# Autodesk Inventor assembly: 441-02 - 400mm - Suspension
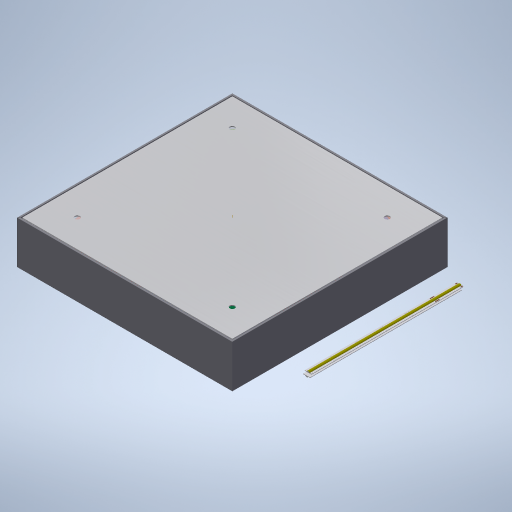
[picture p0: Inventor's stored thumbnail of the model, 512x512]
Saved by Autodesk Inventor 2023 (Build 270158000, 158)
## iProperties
Created: 2022-07
Part Number: 441-02 - 400mm - Suspension
Document SubType Name: Assembly
Designer: DarkStudio
Engineer: DarkStudio
Description: SQUARE MOON 400mm
Manager: DarkStudio
Company: DARK
Mass: 57087.8 g
Surface Area: 45581 cm^2
Volume: 7755.55 cm^3
Density: 7.3609 g/cm^3
Author: DarkStudio
Revision Number: V2
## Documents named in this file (49)
- C:\Users\Stage\Desktop\Stage Karsten\armatures\450 - VIDRYA\450_KARSTEN\3D_LIB_VYDRIA.iam
- D:\Dropbox\003 - DARK 2022\DARK - INVENTOR LOCAL\PROJECT CURRENT\441 - SQUARE MOON\441-001.ipt
- D:\Dropbox\003 - DARK 2022\DARK - INVENTOR LOCAL\PROJECT CURRENT\441 - SQUARE MOON\441-002.ipt
- D:\Dropbox\003 - DARK 2022\DARK - INVENTOR LOCAL\PROJECT CURRENT\441 - SQUARE MOON\441-003.ipt
- D:\Dropbox\003 - DARK 2022\DARK - INVENTOR LOCAL\PROJECT CURRENT\441 - SQUARE MOON\441-004.ipt
- D:\Dropbox\003 - DARK 2022\DARK - INVENTOR LOCAL\PROJECT CURRENT\441 - SQUARE MOON\441-05 + Lightplate and scews.iam
- D:\Dropbox\003 - DARK 2022\DARK - INVENTOR LOCAL\PROJECT CURRENT\441 - SQUARE MOON\441-007.ipt
- D:\Dropbox\003 - DARK 2022\DARK - INVENTOR LOCAL\PROJECT CURRENT\441 - SQUARE MOON\544COB-IP20-2700 - sectie  - 176,4.ipt
- C:\Users\Stage\Desktop\Stage Karsten\armatures\450 - VIDRYA\450-001.ipt
- C:\Users\Stage\Desktop\Stage Karsten\armatures\450 - VIDRYA\450-300 - Sub Assembly Straight Bracket and scew.iam
- C:\Users\Stage\Desktop\Stage Karsten\armatures\450 - VIDRYA\450-002.ipt
- C:\Users\Stage\Desktop\Stage Karsten\armatures\450 - VIDRYA\450-019.ipt
- C:\Users\Stage\Desktop\Stage Karsten\armatures\450 - VIDRYA\450-006.ipt
- C:\Users\Stage\Desktop\Stage Karsten\armatures\450 - VIDRYA\450-008.ipt
- C:\Users\Stage\Desktop\Stage Karsten\armatures\450 - VIDRYA\450-009.ipt
- C:\Users\Stage\Desktop\Stage Karsten\armatures\450 - VIDRYA\450-010.ipt
- C:\Users\Stage\Desktop\Stage Karsten\armatures\450 - VIDRYA\450-011.ipt
- C:\Users\Stage\Desktop\Stage Karsten\armatures\450 - VIDRYA\450-100 - Back-lit panel 295x1195.ipt
- C:\Users\Stage\Desktop\Stage Karsten\armatures\450 - VIDRYA\450-018.ipt
- C:\Users\Stage\Desktop\Stage Karsten\armatures\450 - VIDRYA\450-101 - Back-lit panel UGR-diffusor.ipt
- C:\Users\Stage\Desktop\Stage Karsten\armatures\450 - VIDRYA\450-102 - Back-lit panel diffusor.ipt
- C:\Users\Stage\Desktop\Stage Karsten\armatures\450 - VIDRYA\450-200 - Sub Assembly Brackets and scews DIN916.iam
- C:\Users\Stage\Desktop\Stage Karsten\armatures\450 - VIDRYA\450-004.ipt
- C:\Users\NUUV\Dropbox\003 - DARK 2022\DARK - INVENTOR LOCAL\PROJECT CURRENT\441 - SQUARE MOON - ACTIEF\441-200 - Sub Assembly Brackets and scews ISO7380.iam
- C:\Users\NUUV\Dropbox\003 - DARK 2022\DARK - INVENTOR LOCAL\PROJECT CURRENT\450 - VIDRYA\450-001.ipt
- C:\Users\NUUV\Dropbox\003 - DARK 2022\DARK - INVENTOR LOCAL\PROJECT CURRENT\450 - VIDRYA\450-300 - Sub Assembly Straight Bracket and scew.iam
- C:\Users\NUUV\Dropbox\003 - DARK 2022\DARK - INVENTOR LOCAL\PROJECT CURRENT\450 - VIDRYA\450-002.ipt
- C:\Users\NUUV\Dropbox\003 - DARK 2022\DARK - INVENTOR LOCAL\PROJECT CURRENT\450 - VIDRYA\450-019.ipt
- C:\Users\NUUV\Dropbox\003 - DARK 2022\DARK - INVENTOR LOCAL\PROJECT CURRENT\450 - VIDRYA\450-006.ipt
- C:\Users\NUUV\Dropbox\003 - DARK 2022\DARK - INVENTOR LOCAL\PROJECT CURRENT\450 - VIDRYA\450-008.ipt
- C:\Users\NUUV\Dropbox\003 - DARK 2022\DARK - INVENTOR LOCAL\PROJECT CURRENT\450 - VIDRYA\450-009.ipt
- C:\Users\NUUV\Dropbox\003 - DARK 2022\DARK - INVENTOR LOCAL\PROJECT CURRENT\450 - VIDRYA\450-010.ipt
- C:\Users\NUUV\Dropbox\003 - DARK 2022\DARK - INVENTOR LOCAL\PROJECT CURRENT\450 - VIDRYA\450-011.ipt
- C:\Users\NUUV\Dropbox\003 - DARK 2022\DARK - INVENTOR LOCAL\PROJECT CURRENT\450 - VIDRYA\450-100 - Back-lit panel 295x1195.ipt
- C:\Users\NUUV\Dropbox\003 - DARK 2022\DARK - INVENTOR LOCAL\PROJECT CURRENT\450 - VIDRYA\450-018.ipt
- C:\Users\NUUV\Dropbox\003 - DARK 2022\DARK - INVENTOR LOCAL\PROJECT CURRENT\450 - VIDRYA\450-101 - Back-lit panel UGR-diffusor.ipt
- C:\Users\NUUV\Dropbox\003 - DARK 2022\DARK - INVENTOR LOCAL\PROJECT CURRENT\450 - VIDRYA\450-102 - Back-lit panel diffusor.ipt
- C:\Users\NUUV\Dropbox\003 - DARK 2022\DARK - INVENTOR LOCAL\LIBRARY\ALLERLEI\Splitter Diam 2 B diam. 1.2 O.ipt
- C:\Users\NUUV\Dropbox\003 - DARK 2022\DARK - INVENTOR LOCAL\LIBRARY\ALLERLEI\190-1000-000008.ipt
- C:\Users\NUUV\Dropbox\003 - DARK 2022\DARK - INVENTOR LOCAL\LIBRARY\ALLERLEI\190-1000-000007.ipt
- C:\Users\NUUV\Dropbox\003 - DARK 2022\DARK - INVENTOR LOCAL\LIBRARY\SUSPENSION KITS\190-2012-001500.ipt
- C:\Users\NUUV\Dropbox\003 - DARK 2022\DARK - INVENTOR LOCAL\PROJECT CURRENT\450 - VIDRYA\450-200 - Sub Assembly Brackets and scews DIN916.iam
- C:\Users\NUUV\Dropbox\003 - DARK 2022\DARK - INVENTOR LOCAL\LIBRARY\KABEL ONDERDELEN\Steab - Strain Relief 5331-5.ipt
- C:\Users\NUUV\Dropbox\003 - DARK 2022\DARK - INVENTOR LOCAL\PROJECT CURRENT\225 - PLAFONDPOTJES\225-100.iam
- C:\Users\NUUV\Dropbox\003 - DARK 2022\DARK - INVENTOR LOCAL\PROJECT CURRENT\225 - PLAFONDPOTJES\225-500.iam
- C:\Users\NUUV\Dropbox\003 - DARK 2022\DARK - INVENTOR LOCAL\PROJECT CURRENT\225 - PLAFONDPOTJES\225-640.iam
- C:\Users\NUUV\Dropbox\003 - DARK 2022\DARK - INVENTOR LOCAL\PROJECT CURRENT\225 - PLAFONDPOTJES\225-800.iam
- C:\Users\NUUV\Dropbox\003 - DARK 2022\DARK - INVENTOR LOCAL\PROJECT CURRENT\450 - VIDRYA\450-004.ipt
- C:\Users\NUUV\Dropbox\003 - DARK 2022\DARK - INVENTOR LOCAL\LIBRARY\BEVESTIGING\DIN 7991\M4\DIN 7991 M4 x 8 A2.ipt
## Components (20 placed, 7 different names)
1. 441-002:1 — Mate:3, Mate:4, Flush:6
2. 441-003:1 — Mate:5, Mate:6, Flush:7
3. 441-004:1 — Mate:7, Mate:8, Mate:9, Mate:22
4. 441-007:1 — Mate:23, Mate:24, Mate:25
5. 441-001:1 — Flush:1, Flush:2, Flush:3, Flush:6, Mate:7, Mate:26, Mate:27
6. 441-001:2 — Mate:6, Mate:24
7. 441-001:3 — Mate:8, Mate:25
8. 441-001:4 — Mate:9, Mate:23, Mate:28
9. 544COB-IP20-2700 - sectie  - 176,4:1 — Mate:27, Mate:28
10. 544COB-IP20-2700 - sectie  - 176,4:2
11. 544COB-IP20-2700 - sectie  - 176,4:3
12. 544COB-IP20-2700 - sectie  - 176,4:9
13. 441-05 + Lightplate and scews:1 [sub-assembly]
14. 441-05 + Lightplate and scews:2 [sub-assembly]
15. 441-05 + Lightplate and scews:3 [sub-assembly]
16. 441-05 + Lightplate and scews:4 [sub-assembly]
17. 544COB-IP20-2700 - sectie  - 176,4:5 — Mate:22, Mate:26
18. 544COB-IP20-2700 - sectie  - 176,4:6
19. 544COB-IP20-2700 - sectie  - 176,4:7
20. 544COB-IP20-2700 - sectie  - 176,4:8
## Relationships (19: Mate 14, Flush 5)
- Flush:1: 441-001:1
- Flush:2: 441-001:1
- Flush:3: 441-001:1
- Mate:3: 441-002:1
- Mate:4: 441-002:1
- Flush:6: 441-002:1 ↔ 441-001:1
- Mate:5: 441-003:1
- Mate:6: 441-003:1 ↔ 441-001:2
- Flush:7: 441-003:1
- Mate:7: 441-004:1 ↔ 441-001:1
- Mate:8: 441-004:1 ↔ 441-001:3
- Mate:9: 441-004:1 ↔ 441-001:4
- Mate:22: 441-004:1 ↔ 544COB-IP20-2700 - sectie  - 176,4:5
- Mate:23: 441-007:1 ↔ 441-001:4
- Mate:24: 441-007:1 ↔ 441-001:2
- Mate:25: 441-007:1 ↔ 441-001:3
- Mate:26: 441-001:1 ↔ 544COB-IP20-2700 - sectie  - 176,4:5
- Mate:27: 441-001:1 ↔ 544COB-IP20-2700 - sectie  - 176,4:1
- Mate:28: 441-001:4 ↔ 544COB-IP20-2700 - sectie  - 176,4:1
